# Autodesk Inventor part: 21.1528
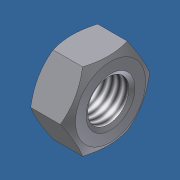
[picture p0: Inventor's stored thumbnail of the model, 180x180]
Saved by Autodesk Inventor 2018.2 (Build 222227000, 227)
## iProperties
Created: 2006-02
Part Number: 21.1528
Material: Steel, Mild
Description: M12 HEX NUT
Document SubType Name: Modeling
Standard: DIN 934
Designer: Andy Moles
Standards Organization: DIN
Language: en-US
Size Designation: M12
Categories: <MemberInstance><Categories><Category DisplayName="Fasteners" InternalName="e4da775c-781d-43d5-af7c-5136215cf5a6" Mnemonic="FSTN"><Category DisplayName="Nuts" I
Density: 7.85 g/cm^3
Mass: 17.5413 g
Surface Area: 13.3413 cm^2
Volume: 2.23456 cm^3
Appearance: Zinc
Author: Andy Moles
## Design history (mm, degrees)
sketch "Sketch1"
  geometry: L1 (-10.97, 0)-(-5.485, 9.5); L2 (-5.485, 9.5)-(5.485, 9.5); L3 (5.485, 9.5)-(10.97, 0); L4 (10.97, 0)-(5.485, -9.5); L5 (5.485, -9.5)-(-5.485, -9.5); L6 (-5.485, -9.5)-(-10.97, 0); 2 further points
  constraints: 12 end point, 1 coincident, 1 horizontal, 11 other
  dimensions: "d0" = 21.93931 distance of L3.end L1.start (= 1.1547 x SW)
extrude "Body" new body sketch "Sketch1" distance "d1" = 10 (= KOH); taper "d2" = 0 deg
sketch "Sketch2"
  geometry: L1 (0, 5.485)-(0, 10.97) reference; L2 (0, 10.97)-(10, 10.97) reference; L3 (10, 5.485)-(10, 10.97) reference; L4 (-1, 0)-(13, 0) reference; L5 (1.368, 10.97)-(0, 8.6); L6 (8.632, 10.97)-(10, 8.6)
  constraints: 4 end point, 4 point on line
  dimensions: "d3" = 30 deg angle of L1 L5 (= ANG1); "d4" = 30 deg angle of L3 L6 (= ANG2); "d5" = 17.2 diameter of L5.end L4 (= SW0); "d6" = 17.2 diameter of L6.end L4 (= SW01)
revolve "Chamfer1" sketch "Sketch2" stored, may be unused: angle "d7" = 90 deg
sketch "Sketch3"
  geometry: 4 further points
  constraints: 1 coincident, 1 other
hole "Thread" sketch "Sketch3" at (0, 0) diameter "d25" = 10.106; stored, may be unused: countersink angle "d29" = 82 deg, drill point angle "d31" = 118 deg; dims "d26" = 6, "d27" = 4, "d28" = 2, "d30" = 8
workaxis "Work Axis1"
workplane "Work Plane1"
body "Solid1"
chamfer "Chamfer2" distance "d8" = 0.94722 (= -0.5 x GD1 + 0.5 x NND); stored, may be unused: angle "d9" = 30 deg, second distance "d40" = 0.94722 (= -0.5 x GD1 + 0.5 x NND)
chamfer "Chamfer3" distance "d10" = 0.94722 (= -0.5 x GD1 + 0.5 x NND); stored, may be unused: angle "d11" = 30 deg, second distance "d41" = 0.94722 (= -0.5 x GD1 + 0.5 x NND)
other parameters: "ANG1" = 30 deg [user parameter; used in 1 equation term], "ANG2" = 30 deg [user parameter; used in 1 equation term], "NND" = 12 [user parameter; used in 4 equation terms], "KOH" = 10 [user parameter; used in 1 equation term], "SW" = 19 [user parameter; used in 2 equation terms], "SW0" = 17.2 (= SW01) [user parameter; used in 1 equation term], "SW01" = 17.2 [user parameter; used in 2 equation terms], "GD1" = 10.10557 (computed from THREADDIA, PTC, TOA) [user parameter; used in 4 equation terms], "d13" = 0, "d14" = 0, "d39" = 0, "d42" = 0, "GUL" = 0.94722 (= 0.541266 x PTC) [user parameter], "TPU" = 5.71429 (computed from PTC) [user parameter], "THREADDIA" = 12 [user parameter; used in 1 equation term], "TOA" = 30 deg [user parameter; used in 1 equation term], "PTC" = 1.75 [user parameter; used in 4 equation terms], "E0" = 21.945 (= 1.155 x SW) [user parameter], "GAL" = 0.94722 (= 0.541266 x PTC) [user parameter]
